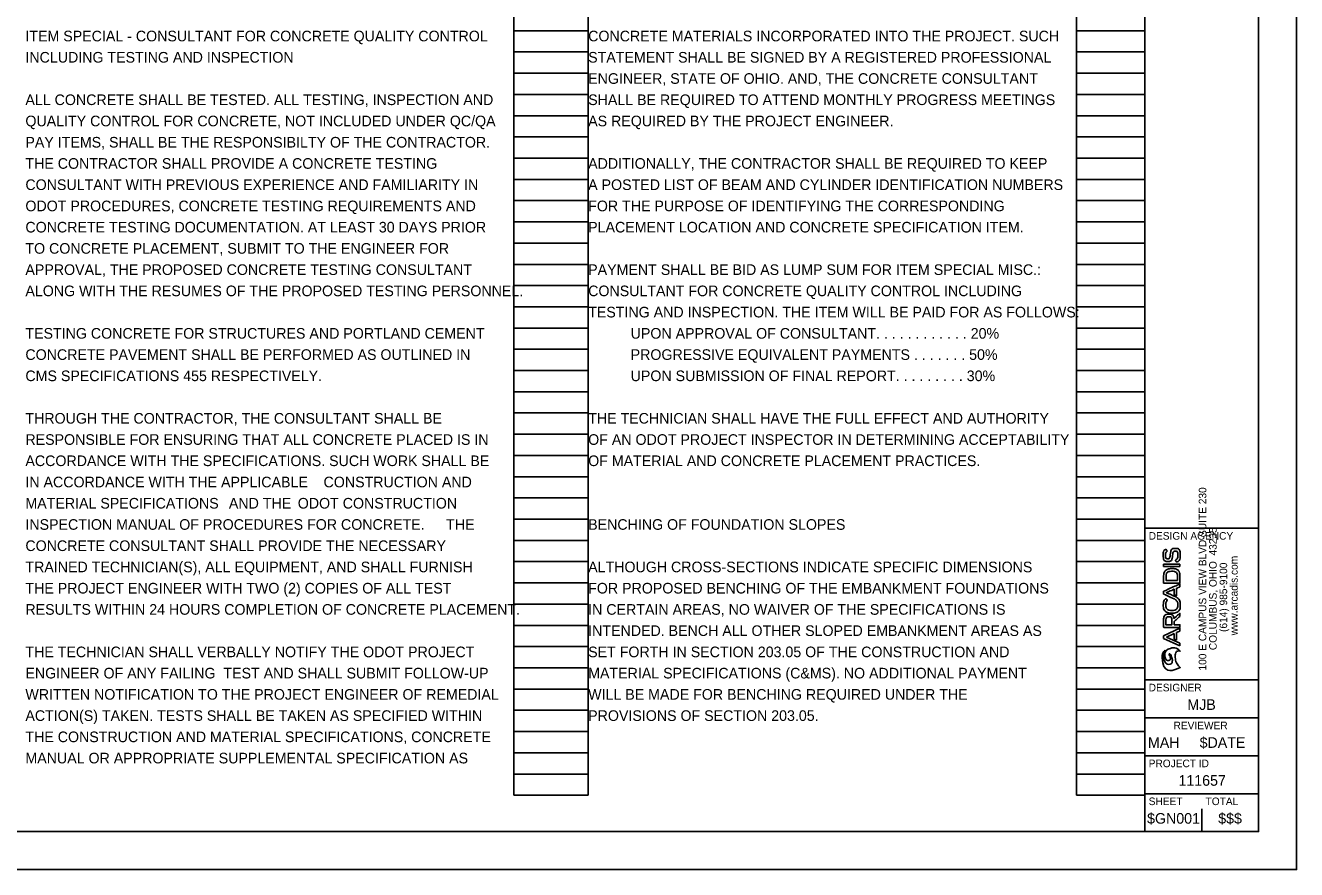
# Model space of a CAD drawing. Extents: x 0 to 76.4, y -34.8 to 22.7.
# Drawn here: x 17.24 to 34, y 0 to 11.13 of the extents above; entities that cross this region are included whole.
import ezdxf

# ---------------------------------------------------------------- set-up
doc = ezdxf.new("R2010")
doc.units = 0
for name, color, linetype in [('SH_Border', 7, 'Continuous'), ('SH_Cut_Line', 7, 'Continuous'), ('SH_Data', 7, 'Continuous'), ('SH_Text', 7, 'Continuous')]:
    doc.layers.add(name, color=color, linetype=linetype)

msp = doc.modelspace()

# ---------------------------------------------------------------- linework, layer by layer
at = {"layer": 'SH_Border'}
for p, q in [((32, 0.5), (32, 21.5)), ((32, 4.5), (33.5, 4.5)), ((32, 2.5), (33.5, 2.5)), ((32, 2), (33.5, 2)), ((32, 1.5), (33.5, 1.5)), ((32, 1), (33.5, 1))]:
    msp.add_line(p, q, dxfattribs=at)
msp.add_lwpolyline([(1.5, 21.5), (33.5, 21.5), (33.5, 0.5), (1.5, 0.5)], close=True, dxfattribs=at)
at = {"layer": 'SH_Cut_Line'}
msp.add_lwpolyline([(0, 0), (34, 0), (34, 22), (0, 22)], close=True, dxfattribs=at)
at = {"layer": 'SH_Data'}
for p, q in [((23.68, 0.98), (23.68, 21.14)), ((24.66, 0.98), (24.66, 21.14)), ((31.1, 0.98), (31.1, 21.14)), ((32, 0.98), (32, 21.14)), ((23.68, 11.06), (24.66, 11.06)), ((31.1, 11.06), (32, 11.06)), ((23.68, 10.78), (24.66, 10.78)), ((31.1, 10.78), (32, 10.78)), ((23.68, 10.5), (24.66, 10.5)), ((31.1, 10.5), (32, 10.5)), ((23.68, 10.22), (24.66, 10.22)), ((31.1, 10.22), (32, 10.22)), ((23.68, 9.94), (24.66, 9.94)), ((31.1, 9.94), (32, 9.94)), ((23.68, 9.66), (24.66, 9.66)), ((31.1, 9.66), (32, 9.66)), ((23.68, 9.38), (24.66, 9.38)), ((31.1, 9.38), (32, 9.38)), ((23.68, 9.1), (24.66, 9.1)), ((31.1, 9.1), (32, 9.1)), ((23.68, 8.82), (24.66, 8.82)), ((31.1, 8.82), (32, 8.82)), ((23.68, 8.54), (24.66, 8.54)), ((31.1, 8.54), (32, 8.54)), ((23.68, 8.26), (24.66, 8.26)), ((31.1, 8.26), (32, 8.26)), ((23.68, 7.98), (24.66, 7.98)), ((31.1, 7.98), (32, 7.98)), ((23.68, 7.7), (24.66, 7.7)), ((31.1, 7.7), (32, 7.7)), ((23.68, 7.42), (24.66, 7.42)), ((31.1, 7.42), (32, 7.42)), ((23.68, 7.14), (24.66, 7.14)), ((31.1, 7.14), (32, 7.14)), ((23.68, 6.86), (24.66, 6.86)), ((31.1, 6.86), (32, 6.86)), ((23.68, 6.58), (24.66, 6.58)), ((31.1, 6.58), (32, 6.58)), ((23.68, 6.3), (24.66, 6.3)), ((31.1, 6.3), (32, 6.3)), ((23.68, 6.02), (24.66, 6.02)), ((31.1, 6.02), (32, 6.02)), ((23.68, 5.74), (24.66, 5.74)), ((31.1, 5.74), (32, 5.74)), ((23.68, 5.46), (24.66, 5.46)), ((31.1, 5.46), (32, 5.46)), ((23.68, 5.18), (24.66, 5.18)), ((31.1, 5.18), (32, 5.18)), ((23.68, 4.9), (24.66, 4.9)), ((31.1, 4.9), (32, 4.9)), ((23.68, 4.62), (24.66, 4.62)), ((31.1, 4.62), (32, 4.62)), ((23.68, 4.34), (24.66, 4.34)), ((31.1, 4.34), (32, 4.34)), ((23.68, 4.06), (24.66, 4.06)), ((31.1, 4.06), (32, 4.06)), ((32.462, 4.028), (32.247, 4.028)), ((32.247, 4.028), (32.247, 3.994)), ((32.462, 3.994), (32.462, 4.028)), ((32.247, 3.994), (32.462, 3.994)), ((23.68, 3.78), (24.66, 3.78)), ((31.1, 3.78), (32, 3.78)), ((23.68, 3.5), (24.66, 3.5)), ((31.1, 3.5), (32, 3.5)), ((32.705, 3.506), (32.705, 3.506)), ((32.75, 3.5), (32.75, 3.5)), ((23.68, 3.22), (24.66, 3.22)), ((31.1, 3.22), (32, 3.22)), ((32.462, 3.181), (32.247, 3.084)), ((32.247, 3.084), (32.247, 3.047)), ((32.247, 3.047), (32.462, 2.95)), ((32.283, 3.066), (32.386, 3.111)), ((32.462, 2.987), (32.283, 3.066)), ((32.386, 3.111), (32.386, 3.04)), ((32.386, 3.04), (32.417, 3.026)), ((32.417, 3.125), (32.462, 3.144)), ((32.417, 3.026), (32.417, 3.125)), ((32.462, 3.144), (32.462, 3.181)), ((23.68, 2.94), (24.66, 2.94)), ((31.1, 2.94), (32, 2.94)), ((32.462, 2.95), (32.462, 2.987)), ((23.68, 2.66), (24.66, 2.66)), ((31.1, 2.66), (32, 2.66)), ((23.68, 2.38), (24.66, 2.38)), ((31.1, 2.38), (32, 2.38)), ((23.68, 2.1), (24.66, 2.1)), ((31.1, 2.1), (32, 2.1)), ((23.68, 1.82), (24.66, 1.82)), ((31.1, 1.82), (32, 1.82)), ((23.68, 1.54), (24.66, 1.54)), ((31.1, 1.54), (32, 1.54)), ((23.68, 1.26), (24.66, 1.26)), ((31.1, 1.26), (32, 1.26)), ((23.68, 0.98), (24.66, 0.98)), ((31.1, 0.98), (32, 0.98)), ((32.375, 0.675), (32.375, 0.675)), ((32.75, 0.5), (32.75, 0.8))]:
    msp.add_line(p, q, dxfattribs=at)
for points, degree in [([(32.295, 4.199), (32.28, 4.189), (32.271, 4.168), (32.271, 4.146), (32.271, 4.117), (32.283, 4.096), (32.303, 4.096), (32.324, 4.096), (32.33, 4.12), (32.334, 4.148), (32.34, 4.193), (32.352, 4.235), (32.401, 4.235), (32.449, 4.235), (32.467, 4.19), (32.467, 4.146), (32.467, 4.104), (32.455, 4.073), (32.418, 4.053), (32.418, 4.053), (32.401, 4.079), (32.401, 4.079), (32.427, 4.094), (32.436, 4.121), (32.436, 4.146), (32.436, 4.172), (32.428, 4.2), (32.401, 4.2), (32.377, 4.2), (32.369, 4.175), (32.365, 4.145), (32.36, 4.102), (32.349, 4.062), (32.303, 4.062), (32.258, 4.062), (32.241, 4.106), (32.241, 4.145), (32.241, 4.176), (32.248, 4.207), (32.277, 4.225), (32.277, 4.225), (32.295, 4.199), (32.295, 4.199), (32.295, 4.199), (32.295, 4.199), (32.295, 4.199)], 3), ([(32.247, 3.778), (32.247, 3.778), (32.462, 3.778), (32.462, 3.778), (32.462, 3.778), (32.462, 3.859), (32.462, 3.859), (32.462, 3.935), (32.407, 3.969), (32.353, 3.968), (32.299, 3.967), (32.247, 3.933), (32.247, 3.859)], 3), ([(32.247, 3.859), (32.247, 3.859), (32.247, 3.778), (32.247, 3.778)], 2), ([(32.28, 3.812), (32.28, 3.812), (32.28, 3.859), (32.28, 3.859), (32.28, 3.91), (32.316, 3.932), (32.352, 3.933), (32.39, 3.934), (32.429, 3.912), (32.429, 3.859), (32.429, 3.859), (32.429, 3.812), (32.429, 3.812)], 3), ([(32.247, 3.669), (32.247, 3.669), (32.247, 3.632), (32.247, 3.632), (32.247, 3.632), (32.387, 3.569), (32.387, 3.569), (32.387, 3.569), (32.387, 3.569), (32.387, 3.569), (32.4, 3.562), (32.408, 3.555), (32.411, 3.552), (32.426, 3.537), (32.434, 3.515), (32.434, 3.495), (32.434, 3.44), (32.395, 3.416), (32.356, 3.416), (32.316, 3.416), (32.276, 3.441), (32.276, 3.495), (32.276, 3.515), (32.283, 3.536), (32.298, 3.551), (32.298, 3.551), (32.276, 3.574), (32.276, 3.574), (32.254, 3.552), (32.243, 3.524), (32.243, 3.495), (32.243, 3.418), (32.299, 3.382), (32.356, 3.382), (32.413, 3.382), (32.467, 3.417), (32.467, 3.495), (32.467, 3.526), (32.456, 3.554), (32.435, 3.576), (32.435, 3.576), (32.421, 3.59), (32.401, 3.599), (32.401, 3.599), (32.395, 3.602), (32.395, 3.602), (32.395, 3.602), (32.38, 3.608), (32.38, 3.608), (32.38, 3.608), (32.38, 3.608), (32.38, 3.608), (32.38, 3.608), (32.283, 3.651), (32.283, 3.651), (32.283, 3.651), (32.386, 3.696), (32.386, 3.696), (32.386, 3.696), (32.386, 3.624), (32.386, 3.624), (32.386, 3.624), (32.417, 3.611), (32.417, 3.611), (32.417, 3.611), (32.417, 3.709), (32.417, 3.709), (32.417, 3.709), (32.462, 3.729), (32.462, 3.729), (32.462, 3.729), (32.462, 3.766), (32.462, 3.766), (32.462, 3.766), (32.247, 3.669), (32.247, 3.669), (32.247, 3.669), (32.247, 3.669), (32.247, 3.669)], 3), ([(32.429, 3.812), (32.429, 3.812), (32.28, 3.812), (32.28, 3.812)], 2), ([(32.384, 3.311), (32.378, 3.353), (32.348, 3.369), (32.317, 3.369), (32.281, 3.369), (32.247, 3.343), (32.247, 3.293), (32.247, 3.26), (32.247, 3.226), (32.247, 3.193), (32.247, 3.193), (32.462, 3.193), (32.462, 3.193), (32.462, 3.193), (32.462, 3.227), (32.462, 3.227), (32.462, 3.227), (32.388, 3.227), (32.388, 3.227), (32.388, 3.227), (32.388, 3.273), (32.388, 3.273), (32.388, 3.273), (32.462, 3.339), (32.462, 3.339), (32.462, 3.339), (32.462, 3.379), (32.462, 3.379)], 3), ([(32.462, 3.379), (32.462, 3.379), (32.384, 3.311), (32.384, 3.311)], 2), ([(32.278, 3.293), (32.278, 3.322), (32.299, 3.334), (32.318, 3.334), (32.338, 3.334), (32.356, 3.322), (32.356, 3.293), (32.356, 3.293), (32.356, 3.227), (32.356, 3.227), (32.356, 3.227), (32.278, 3.227), (32.278, 3.227)], 3), ([(32.278, 3.227), (32.278, 3.227), (32.278, 3.293), (32.278, 3.293)], 2), ([(32.227, 2.792), (32.237, 2.58), (32.469, 2.662), (32.469, 2.662), (32.449, 2.68), (32.401, 2.74), (32.401, 2.823), (32.401, 2.823), (32.401, 2.823), (32.401, 2.823), (32.401, 2.863), (32.435, 2.887), (32.469, 2.878), (32.469, 2.878), (32.396, 2.941), (32.312, 2.906), (32.284, 2.894), (32.264, 2.863), (32.264, 2.826), (32.264, 2.814), (32.266, 2.801), (32.271, 2.788), (32.284, 2.757), (32.311, 2.753), (32.324, 2.76), (32.333, 2.764), (32.338, 2.773), (32.338, 2.783), (32.338, 2.785), (32.338, 2.786), (32.338, 2.788), (32.333, 2.819), (32.319, 2.831), (32.319, 2.838), (32.319, 2.839), (32.319, 2.84), (32.32, 2.841), (32.323, 2.846), (32.337, 2.841), (32.353, 2.802), (32.357, 2.792), (32.362, 2.775), (32.362, 2.758), (32.362, 2.738), (32.356, 2.718), (32.335, 2.711), (32.298, 2.699), (32.253, 2.743), (32.247, 2.81), (32.247, 2.813), (32.247, 2.818), (32.247, 2.821), (32.247, 2.855), (32.262, 2.879), (32.272, 2.891), (32.249, 2.877), (32.228, 2.848), (32.227, 2.801), (32.227, 2.801), (32.227, 2.798), (32.227, 2.792), (32.227, 2.792), (32.227, 2.792), (32.227, 2.792)], 3)]:
    msp.add_open_spline(points, degree=degree, dxfattribs=at)

# ---------------------------------------------------------------- texts
for s, p in [('100 E CAMPUS VIEW BLVD SUITE 230', (32.81, 2.625)), ('COLUMBUS, OHIO  43235', (32.947, 2.893)), ('(614) 985-9100', (33.085, 3.133)), ('www.arcadis.com', (33.223, 3.089))]:
    msp.add_text(s, height=0.1, rotation=90, dxfattribs=at).set_placement(p)
for s, height, p in [('DESIGN AGENCY', 0.1, (32.05, 4.35)), ('DESIGNER', 0.1, (32.05, 2.35)), ('MJB', 0.14, (32.56, 2.105)), ('REVIEWER', 0.1, (32.378, 1.85)), ('MAH', 0.14, (32.041, 1.605)), ('$DATE', 0.14, (32.722, 1.605)), ('PROJECT ID', 0.1, (32.05, 1.35)), ('111657', 0.14, (32.443, 1.105)), ('SHEET', 0.1, (32.05, 0.85)), ('TOTAL', 0.1, (32.8, 0.85)), ('$GN001', 0.14, (32.029, 0.605)), ('$$$', 0.14, (32.967, 0.605))]:
    msp.add_text(s, height=height, dxfattribs=at).set_placement(p)
at = {"layer": 'SH_Text'}
for s, p in [('ITEM SPECIAL - CONSULTANT FOR CONCRETE QUALITY CONTROL', (17.24, 10.92)), ('CONCRETE MATERIALS INCORPORATED INTO THE PROJECT. SUCH', (24.66, 10.92)), ('INCLUDING TESTING AND INSPECTION', (17.24, 10.64)), ('STATEMENT SHALL BE SIGNED BY A REGISTERED PROFESSIONAL', (24.66, 10.64)), ('ENGINEER, STATE OF OHIO. AND, THE CONCRETE CONSULTANT', (24.66, 10.36)), ('ALL CONCRETE SHALL BE TESTED. ALL TESTING, INSPECTION AND', (17.24, 10.08)), ('SHALL BE REQUIRED TO ATTEND MONTHLY PROGRESS MEETINGS', (24.66, 10.08)), ('QUALITY CONTROL FOR CONCRETE, NOT INCLUDED UNDER QC/QA', (17.24, 9.8)), ('AS REQUIRED BY THE PROJECT ENGINEER.', (24.66, 9.8)), ('PAY ITEMS, SHALL BE THE RESPONSIBILTY OF THE CONTRACTOR.', (17.24, 9.52)), ('THE CONTRACTOR SHALL PROVIDE A CONCRETE TESTING', (17.24, 9.24)), ('ADDITIONALLY, THE CONTRACTOR SHALL BE REQUIRED TO KEEP', (24.66, 9.24)), ('CONSULTANT WITH PREVIOUS EXPERIENCE AND FAMILIARITY IN', (17.24, 8.96)), ('A POSTED LIST OF BEAM AND CYLINDER IDENTIFICATION NUMBERS', (24.66, 8.96)), ('ODOT PROCEDURES, CONCRETE TESTING REQUIREMENTS AND', (17.24, 8.68)), ('FOR THE PURPOSE OF IDENTIFYING THE CORRESPONDING', (24.66, 8.68)), ('CONCRETE TESTING DOCUMENTATION. AT LEAST 30 DAYS PRIOR', (17.24, 8.4)), ('PLACEMENT LOCATION AND CONCRETE SPECIFICATION ITEM.', (24.66, 8.4)), ('TO CONCRETE PLACEMENT, SUBMIT TO THE ENGINEER FOR', (17.24, 8.12)), ('APPROVAL, THE PROPOSED CONCRETE TESTING CONSULTANT', (17.24, 7.84)), ('PAYMENT SHALL BE BID AS LUMP SUM FOR ITEM SPECIAL MISC.:', (24.66, 7.84)), ('ALONG WITH THE RESUMES OF THE PROPOSED TESTING PERSONNEL.', (17.24, 7.56)), ('CONSULTANT FOR CONCRETE QUALITY CONTROL INCLUDING', (24.66, 7.56)), ('TESTING AND INSPECTION. THE ITEM WILL BE PAID FOR AS FOLLOWS:', (24.66, 7.28)), ('TESTING CONCRETE FOR STRUCTURES AND PORTLAND CEMENT', (17.24, 7)), ('UPON APPROVAL OF CONSULTANT. . . . . . . . . . . . 20%', (25.22, 7)), ('CONCRETE PAVEMENT SHALL BE PERFORMED AS OUTLINED IN', (17.24, 6.72)), ('PROGRESSIVE EQUIVALENT PAYMENTS . . . . . . . 50%', (25.22, 6.72)), ('CMS SPECIFICATIONS 455 RESPECTIVELY.', (17.24, 6.44)), ('UPON SUBMISSION OF FINAL REPORT. . . . . . . . . 30%', (25.22, 6.44)), ('THROUGH THE CONTRACTOR, THE CONSULTANT SHALL BE', (17.24, 5.88)), ('THE TECHNICIAN SHALL HAVE THE FULL EFFECT AND AUTHORITY', (24.66, 5.88)), ('RESPONSIBLE FOR ENSURING THAT ALL CONCRETE PLACED IS IN', (17.24, 5.6)), ('OF AN ODOT PROJECT INSPECTOR IN DETERMINING ACCEPTABILITY', (24.66, 5.6)), ('ACCORDANCE WITH THE SPECIFICATIONS. SUCH WORK SHALL BE', (17.24, 5.32)), ('OF MATERIAL AND CONCRETE PLACEMENT PRACTICES.', (24.66, 5.32)), ('IN ACCORDANCE WITH THE APPLICABLE ', (17.24, 5.04)), ('CONSTRUCTION AND', (21.171, 5.04)), ('MATERIAL SPECIFICATIONS', (17.24, 4.76)), (' AND THE ', (19.871, 4.76)), ('ODOT CONSTRUCTION', (20.831, 4.76)), ('INSPECTION MANUAL OF PROCEDURES FOR CONCRETE.', (17.24, 4.48)), ('THE', (22.787, 4.48)), ('BENCHING OF FOUNDATION SLOPES', (24.66, 4.48)), ('CONCRETE CONSULTANT SHALL PROVIDE THE NECESSARY', (17.24, 4.2)), ('TRAINED TECHNICIAN(S), ALL EQUIPMENT, AND SHALL FURNISH', (17.24, 3.92)), ('ALTHOUGH CROSS-SECTIONS INDICATE SPECIFIC DIMENSIONS', (24.66, 3.92)), ('THE PROJECT ENGINEER WITH TWO (2) COPIES OF ALL TEST', (17.24, 3.64)), ('FOR PROPOSED BENCHING OF THE EMBANKMENT FOUNDATIONS', (24.66, 3.64)), ('RESULTS WITHIN 24 HOURS COMPLETION OF CONCRETE PLACEMENT.', (17.24, 3.36)), ('IN CERTAIN AREAS, NO WAIVER OF THE SPECIFICATIONS IS', (24.66, 3.36)), ('INTENDED. BENCH ALL OTHER SLOPED EMBANKMENT AREAS AS', (24.66, 3.08)), ('THE TECHNICIAN SHALL VERBALLY NOTIFY THE ODOT PROJECT', (17.24, 2.8)), ('SET FORTH IN SECTION 203.05 OF THE CONSTRUCTION AND', (24.66, 2.8)), ('ENGINEER OF ANY FAILING  TEST AND SHALL SUBMIT FOLLOW-UP', (17.24, 2.52)), ('MATERIAL SPECIFICATIONS (C&MS). NO ADDITIONAL PAYMENT', (24.66, 2.52)), ('WRITTEN NOTIFICATION TO THE PROJECT ENGINEER OF REMEDIAL', (17.24, 2.24)), ('WILL BE MADE FOR BENCHING REQUIRED UNDER THE', (24.66, 2.24)), ('ACTION(S) TAKEN. TESTS SHALL BE TAKEN AS SPECIFIED WITHIN', (17.24, 1.96)), ('PROVISIONS OF SECTION 203.05.', (24.66, 1.96)), ('THE CONSTRUCTION AND MATERIAL SPECIFICATIONS, CONCRETE', (17.24, 1.68)), ('MANUAL OR APPROPRIATE SUPPLEMENTAL SPECIFICATION AS', (17.24, 1.4))]:
    msp.add_text(s, height=0.14, dxfattribs=at).set_placement(p)

doc.saveas('drawing.dxf')
